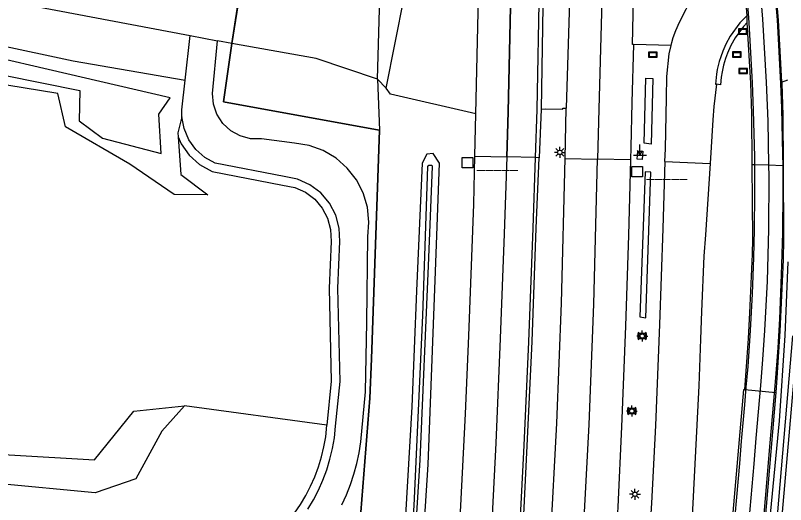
# Model space of a CAD drawing. Extents: x 124000 to 129000, y 395500 to 397503.
# Drawn here: x 124745.4 to 124833.3, y 397160 to 397215.8 of the extents above; entities that cross this region are included whole.
import ezdxf

# ---------------------------------------------------------------- set-up
doc = ezdxf.new("R2010")
doc.units = 0
for name, color, linetype in [('gg-afsc-hekwerk', 7, 'Continuous'), ('gg-afsc-muur', 7, 'Continuous'), ('gg-knt-BGT kruinlijn', 7, 'Continuous'), ('gt-symb-bord', 7, 'Continuous'), ('gt-symb-hm paal', 7, 'Continuous'), ('gt-symb-lichtmast', 7, 'Continuous'), ('gt-symb-markant object', 7, 'Continuous'), ('gx-grn-maaiveld', 7, 'Continuous'), ('gx-knt-lijn weginrichtingselement', 7, 'Continuous')]:
    doc.layers.add(name, color=color, linetype=linetype)

# ---------------------------------------------------------------- blocks, each defined once
blk = doc.blocks.new('gt0-BORD')
at = {"layer": 'gt-symb-bord'}
blk.add_lwpolyline([(-0.5, 0.295), (-0.5, -0.295), (0.5, -0.295), (0.5, 0.295), (-0.5, 0.295)], dxfattribs=at)
blk.add_lwpolyline([(-0.417, -0.212), (0.417, -0.212), (0.417, 0.212), (-0.417, 0.212)], close=True, dxfattribs=at)
blk = doc.blocks.new('gt0-LMAST')
at = {"layer": 'gt-symb-lichtmast'}
for p, q in [((-0.182, 0.173), (-0.447, 0.438)), ((-0.005, 0.246), (-0.005, 0.621)), ((0.172, 0.173), (0.437, 0.438)), ((-0.255, -0.004), (-0.63, -0.004)), ((-0.182, -0.181), (-0.447, -0.446)), ((-0.005, -0.254), (-0.005, -0.629)), ((0.437, -0.446), (0.172, -0.181)), ((0.245, -0.004), (0.62, -0.004))]:
    blk.add_line(p, q, dxfattribs=at)
blk.add_circle((-0.005, -0.004), 0.25, dxfattribs=at)
blk = doc.blocks.new('gt0-HMpaal')
at = {"layer": 'gt-symb-hm paal'}
blk.add_lwpolyline([(-0.6, 0.6), (0.6, 0.6), (0.6, -0.6), (-0.6, -0.6)], close=True, dxfattribs=at)
blk = doc.blocks.new('gt0-MARKOB')
at = {"layer": 'gt-symb-markant object'}
for p, q in [((0, 0), (0, 1.2)), ((-0.75, 0), (0.75, 0)), ((0, 0), (-0.3, 0.52)), ((0, 0), (0.3, 0.52))]:
    blk.add_line(p, q, dxfattribs=at)

msp = doc.modelspace()

# ---------------------------------------------------------------- linework, layer by layer
at = {"layer": 'gg-afsc-hekwerk'}
msp.add_lwpolyline([(124774.888, 397073.073), (124778.544, 397099.23), (124778.986, 397102.392), (124782.98, 397135.974), (124785.856, 397172.14), (124786.014, 397176.607), (124786.937, 397202.711), (124786.926, 397202.713)], dxfattribs=at)
at = {"layer": 'gg-afsc-muur'}
msp.add_lwpolyline([(124786.926, 397202.713), (124769.12, 397205.943), (124770.099, 397212.604), (124771.041, 397218.798), (124772.03, 397225.418)], dxfattribs=at)
at = {"layer": 'gg-knt-BGT kruinlijn'}
for points in [[(124744.044, 397208.989), (124752.708, 397207.237), (124752.633, 397203.786), (124755.318, 397201.798), (124762.031, 397200.056), (124761.73, 397204.56), (124763.041, 397206.421), (124729.225, 397214.239)], [(124734.86, 397166.221), (124754.384, 397165.109), (124758.906, 397170.639), (124764.666, 397171.269)]]:
    msp.add_lwpolyline(points, dxfattribs=at)
at = {"layer": 'gx-grn-maaiveld'}
for p, q in [((124787.696, 397207.503), (124790.039, 397219.245)), ((124797.958, 397204.587), (124798.269, 397219.426)), ((124771.041, 397218.798), (124770.099, 397212.604)), ((124786.713, 397208.551), (124787.002, 397218.335)), ((124741.693, 397218.013), (124765.335, 397213.524)), ((124828.951, 397215.035), (124828.924, 397215.803)), ((124764.759, 397208.43), (124765.335, 397213.524)), ((124765.335, 397213.524), (124768.438, 397212.931)), ((124770.099, 397212.604), (124768.438, 397212.931)), ((124820.245, 397212.407), (124815.953, 397212.51)), ((124786.713, 397208.551), (124786.937, 397202.711)), ((124786.713, 397208.551), (124787.696, 397207.503)), ((124832.867, 397208.207), (124833.564, 397208.483)), ((124805.396, 397205.136), (124805.175, 397199.578)), ((124808.133, 397199.508), (124808.278, 397205.238)), ((124797.844, 397199.75), (124797.958, 397204.587)), ((124797.844, 397199.75), (124801.477, 397199.665)), ((124808.133, 397199.508), (124811.832, 397199.421)), ((124815.623, 397199.331), (124811.832, 397199.421)), ((124819.55, 397199.157), (124824.71, 397198.93)), ((124828.661, 397173.125), (124832.203, 397172.797)), ((124780.94, 397169.071), (124764.666, 397171.269))]:
    msp.add_line(p, q, dxfattribs=at)
for points in [[(124801.477, 397199.665), (124801.648, 397204.803), (124801.931, 397218.564), (124802.042, 397226.77), (124802.168, 397238.749), (124802.175, 397247.682), (124802.181, 397259.638), (124802.019, 397274.636), (124801.88, 397286.592), (124801.727, 397298.073), (124801.711, 397299.476)], [(124812.013, 397299.605), (124812.033, 397298.079), (124812.547, 397250.06), (124812.38, 397224.092), (124812.299, 397216.177), (124811.977, 397205.137), (124811.832, 397199.421)], [(124815.953, 397212.51), (124815.856, 397212.503), (124816.124, 397224.643), (124816.158, 397225.374), (124816.219, 397225.384)], [(124820.245, 397212.407), (124820.34, 397212.73), (124820.49, 397213.306), (124820.77, 397214.095), (124821.189, 397215.056), (124821.975, 397216.528), (124822.274, 397217.133), (124822.492, 397217.714), (124822.657, 397218.288), (124822.74, 397218.739), (124822.782, 397219.139), (124822.781, 397219.593), (124822.704, 397220.21), (124822.536, 397220.812), (124822.294, 397221.382), (124821.511, 397222.691), (124820.097, 397224.65), (124819.325, 397225.883), (124819.207, 397225.866)], [(124828.924, 397215.803), (124828.626, 397219.477), (124828.435, 397221.586), (124828.068, 397225.291)], [(124805.725, 397224.171), (124805.645, 397219.25), (124805.396, 397205.136)], [(124808.68, 397224.123), (124808.6, 397216.25), (124808.278, 397205.238)], [(124832.221, 397218.472), (124832.491, 397215.299), (124832.867, 397208.207)], [(124764.666, 397171.269), (124762.075, 397168.382), (124759.111, 397162.908), (124754.494, 397161.316), (124731.985, 397163.453), (124732.038, 397181.857), (124731.048, 397186.807), (124728.725, 397191.298), (124716.329, 397210.851), (124716.4, 397215.823), (124718.656, 397217.804)], [(124718.656, 397217.804), (124751.959, 397210.644), (124764.759, 397208.43)], [(124828.924, 397215.803), (124828.092, 397214.987), (124827.001, 397213.449), (124826.486, 397212.539), (124826.141, 397211.747), (124825.916, 397211.085), (124825.749, 397210.563), (124825.526, 397209.667), (124825.439, 397209.12), (124825.322, 397207.995), (124825.426, 397207.979)], [(124828.951, 397215.035), (124828.534, 397214.579), (124827.581, 397213.26), (124827.058, 397212.389), (124826.673, 397211.508), (124826.472, 397210.909), (124826.228, 397210.136), (124826.066, 397209.404), (124825.977, 397208.778), (124825.898, 397207.894), (124825.426, 397207.979)], [(124829.517, 397198.821), (124829.483, 397204.589), (124829.364, 397208.092), (124828.951, 397215.035)], [(124782.649, 397159.965), (124783.176, 397161.104), (124783.637, 397162.272), (124784.033, 397163.464), (124784.36, 397164.676), (124784.619, 397165.905), (124784.808, 397167.146), (124785.362, 397172.864), (124785.506, 397180.807), (124785.605, 397190.545), (124785.746, 397192.239), (124785.569, 397193.929), (124785.083, 397195.557), (124784.303, 397197.067), (124783.257, 397198.406), (124781.98, 397199.528), (124780.518, 397200.393), (124778.92, 397200.973), (124777.243, 397201.246), (124773.459, 397201.744), (124772.226, 397201.755), (124771.033, 397202.067), (124769.953, 397202.661), (124769.05, 397203.501), (124768.38, 397204.536), (124767.982, 397205.703), (124767.881, 397206.931), (124768.438, 397212.931)], [(124763.95, 397201.974), (124764.244, 397197.65), (124767.342, 397195.356), (124763.494, 397195.393), (124758.451, 397198.841), (124751.085, 397203.119), (124750.195, 397206.931), (124744.4, 397207.852), (124743.31, 397204.027), (124739.841, 397201.078), (124736.645, 397202.425), (124735.857, 397205.839), (124738.727, 397209.291), (124722.615, 397211.997), (124731.01, 397200.841), (124737.714, 397189.35), (124739.363, 397181.16), (124738.979, 397176.47)], [(124770.099, 397212.604), (124769.12, 397205.943), (124786.926, 397202.713), (124786.937, 397202.711)], [(124786.713, 397208.551), (124779.726, 397210.918), (124770.099, 397212.604)], [(124815.953, 397212.51), (124815.777, 397205.87), (124815.664, 397200.769), (124815.623, 397199.331)], [(124819.55, 397199.157), (124819.593, 397200.602), (124819.735, 397206.433), (124819.777, 397208.854), (124820.015, 397211.422), (124820.245, 397212.407)], [(124764.388, 397204.241), (124764.37, 397204.645), (124764.377, 397205.05), (124764.759, 397208.43)], [(124817.379, 397208.662), (124818.176, 397208.643), (124817.966, 397201.122), (124817.171, 397201.253), (124817.379, 397208.662)], [(124825.426, 397207.979), (124825.146, 397205.415), (124825.029, 397203.891), (124824.71, 397198.93)], [(124832.867, 397208.207), (124832.874, 397208.084), (124833.007, 397204.401), (124833.037, 397198.708)], [(124797.958, 397204.587), (124788.219, 397206.853), (124787.696, 397207.503)], [(124805.396, 397205.136), (124805.94, 397205.144), (124807.885, 397205.138), (124807.889, 397205.235), (124808.278, 397205.238)], [(124764.388, 397204.241), (124763.92, 397202.412), (124763.95, 397201.974)], [(124778.747, 397159.452), (124779.394, 397160.527), (124779.974, 397161.639), (124780.485, 397162.785), (124780.925, 397163.96), (124781.291, 397165.16), (124781.583, 397166.38), (124781.798, 397167.594), (124781.931, 397168.937), (124782.438, 397174.042), (124782.197, 397184.679), (124782.415, 397190.004), (124782.353, 397191.547), (124781.952, 397193.038), (124781.233, 397194.405), (124780.231, 397195.58), (124778.994, 397196.504), (124777.584, 397197.134), (124776.07, 397197.437), (124768.183, 397198.945), (124766.993, 397199.618), (124765.976, 397200.531), (124765.18, 397201.642), (124764.642, 397202.898), (124764.388, 397204.241)], [(124786.937, 397202.711), (124786.014, 397176.607), (124785.856, 397172.14), (124782.98, 397135.974), (124778.986, 397102.392), (124778.544, 397099.23), (124774.888, 397073.073)], [(124763.95, 397201.974), (124764.304, 397201.148), (124765.227, 397199.86), (124766.406, 397198.801), (124767.834, 397197.994), (124775.878, 397196.456), (124777.278, 397196.175), (124778.485, 397195.636), (124779.543, 397194.846), (124780.4, 397193.841), (124781.015, 397192.671), (124781.358, 397191.395), (124781.414, 397190.004), (124781.197, 397184.688), (124781.437, 397174.08), (124780.94, 397169.071)], [(124792.493, 397164.558), (124793.336, 397186.577), (124793.792, 397198.942), (124793.076, 397200.057), (124792.365, 397199.989), (124791.803, 397198.95), (124791.169, 397184.399), (124790.651, 397171.158), (124788.93, 397141.752), (124788.332, 397129.544), (124788.772, 397128.809), (124789.791, 397128.882), (124790.18, 397129.594), (124791.418, 397147.308), (124792.493, 397164.558)], [(124792.053, 397100.524), (124792.546, 397105.919), (124793.395, 397116.661), (124794.283, 397128.623), (124794.888, 397137.357), (124795.489, 397146.444), (124796.008, 397155.393), (124796.758, 397170.354), (124797.147, 397179.258), (124797.715, 397194.281), (124797.844, 397199.75)], [(124801.477, 397199.665), (124801.186, 397190.886), (124800.743, 397178.945), (124800.219, 397166.983), (124799.608, 397155.046), (124799.03, 397145.628), (124798.481, 397136.86), (124797.88, 397128.167), (124796.99, 397116.232), (124796.117, 397105.554), (124795.627, 397100.198)], [(124805.175, 397199.578), (124804.728, 397199.588), (124801.477, 397199.665)], [(124817.003, 397200.33), (124816.96, 397199.396), (124816.383, 397199.425), (124816.438, 397200.347), (124817.003, 397200.33)], [(124799.258, 397099.866), (124799.742, 397105.283), (124800.619, 397115.925), (124801.525, 397128.032), (124802.127, 397136.933), (124802.696, 397145.813), (124803.25, 397154.939), (124803.826, 397166.677), (124804.372, 397178.604), (124804.856, 397191.558), (124805.175, 397199.578)], [(124802.693, 397099.552), (124803.862, 397114.352), (124805.745, 397142.189), (124807.181, 397169.292), (124807.714, 397182.987), (124808.133, 397199.508)], [(124806.378, 397099.216), (124807.552, 397114.081), (124809.438, 397141.966), (124810.877, 397169.122), (124811.412, 397182.868), (124811.832, 397199.421)], [(124815.623, 397199.331), (124815.376, 397190.733), (124815.034, 397180.336), (124814.576, 397168.863), (124814.158, 397159.742), (124813.763, 397152.182), (124813.263, 397143.33), (124812.64, 397133.59), (124812.135, 397125.781), (124811.451, 397116.218), (124811.177, 397112.27), (124811.095, 397110.289), (124811.191, 397109.366), (124811.339, 397108.98), (124811.631, 397108.819), (124812.527, 397108.655), (124812.673, 397108.826)], [(124819.55, 397199.157), (124819.322, 397191.497), (124818.937, 397180.542), (124818.477, 397169.025), (124818.007, 397160.137), (124817.508, 397152.544), (124816.784, 397143.505), (124815.742, 397132.649), (124814.96, 397125.558), (124813.712, 397115.965), (124813.219, 397112.169), (124812.673, 397108.826)], [(124824.71, 397198.93), (124824.187, 397190.79), (124823.99, 397188.358), (124823.72, 397182.019), (124823.602, 397178.867), (124823.421, 397173.546), (124822.568, 397157.186), (124821.361, 397141.341), (124820.11, 397129.03), (124818.402, 397115.016), (124816.619, 397102.542), (124815.973, 397098.339)], [(124828.661, 397173.125), (124828.869, 397175.754), (124829.092, 397178.958), (124829.256, 397181.861), (124829.524, 397188.562), (124829.568, 397190.3), (124829.517, 397198.821)], [(124829.517, 397198.821), (124829.763, 397198.813), (124831.372, 397198.761), (124832.988, 397198.709), (124833.037, 397198.708)], [(124789.1, 397130.056), (124789.023, 397130.472), (124789.492, 397138.147), (124790.89, 397159.871), (124791.91, 397181.556), (124792.468, 397198.573), (124792.58, 397198.74), (124792.94, 397198.725), (124792.971, 397198.565), (124792.516, 397187.236), (124791.565, 397165.104), (124790.277, 397144.363), (124789.555, 397130.34), (124789.384, 397130.014), (124789.1, 397130.056)], [(124817.298, 397197.988), (124816.685, 397181.418), (124817.348, 397181.303), (124817.943, 397197.923), (124817.298, 397197.988)], [(124833.037, 397198.708), (124833.081, 397190.289), (124833.038, 397187.93), (124832.669, 397179.781), (124832.308, 397174.447), (124832.203, 397172.797)], [(124833.592, 397151.797), (124832.183, 397137.766), (124829.788, 397119.595), (124826.61, 397097.963), (124824.265, 397083.356), (124823.459, 397082.467), (124822.605, 397082.75), (124822.412, 397083.719), (124824.719, 397099.103), (124826.864, 397114.299), (124828.375, 397125.994), (124830.027, 397141.258), (124831.424, 397156.915), (124832.636, 397169.565), (124833.27, 397179.301), (124833.609, 397187.707)], [(124834.102, 397179.257), (124833.288, 397169.452), (124832.217, 397156.933), (124830.916, 397141.146), (124829.393, 397128.559), (124827.243, 397111.868), (124824.942, 397095.048), (124823.525, 397086.424), (124823.233, 397084.201), (124823.531, 397084.16), (124823.858, 397086.09), (124825.298, 397095.537), (124828.888, 397119.593), (124831.026, 397138.621), (124832.319, 397151.689), (124834.465, 397176.119)], [(124820.123, 397097.96), (124820.735, 397101.935), (124822.587, 397114.679), (124824.332, 397128.574), (124825.822, 397142.192), (124827.162, 397156.872), (124828.552, 397173.108), (124828.661, 397173.125)], [(124832.203, 397172.797), (124830.9, 397157.533), (124829.438, 397141.65), (124827.763, 397126.481), (124826.261, 397114.488), (124824.827, 397104.624), (124823.741, 397097.63)], [(124777.229, 397159.012), (124777.906, 397159.994), (124778.522, 397161.017), (124779.073, 397162.074), (124779.559, 397163.164), (124779.978, 397164.282), (124780.326, 397165.423), (124780.604, 397166.584), (124780.807, 397167.731), (124780.94, 397169.071)]]:
    msp.add_lwpolyline(points, dxfattribs=at)
at = {"layer": 'gx-knt-lijn weginrichtingselement'}
for points in [[(124801.727, 397298.073), (124801.88, 397286.592), (124802.019, 397274.636), (124802.181, 397259.638), (124802.175, 397247.682), (124802.168, 397238.749), (124802.042, 397226.77), (124801.931, 397218.564), (124801.648, 397204.803), (124801.477, 397199.665), (124801.186, 397190.886), (124800.743, 397178.945), (124800.219, 397166.983), (124799.608, 397155.046), (124799.03, 397145.628), (124798.481, 397136.86), (124797.88, 397128.167), (124796.99, 397116.232), (124796.117, 397105.554), (124795.627, 397100.198), (124794.838, 397091.583), (124793.772, 397080.49), (124792.634, 397069.481)], [(124805.19, 397219.294), (124804.912, 397205.094), (124804.728, 397199.588), (124804.459, 397191.552), (124803.98, 397178.573), (124803.44, 397166.73), (124802.819, 397154.917), (124802.282, 397145.871), (124801.719, 397136.946), (124801.105, 397127.897), (124800.186, 397115.87), (124799.346, 397105.252), (124798.867, 397099.902), (124798.088, 397091.191), (124796.986, 397079.888), (124795.848, 397069.031), (124794.092, 397053.296), (124793.359, 397047.038), (124791.835, 397034.538), (124790.748, 397026.333), (124787.672, 397003.903)], [(124828.818, 397219.148), (124829.133, 397215.001), (124829.501, 397208.122), (124829.631, 397204.957), (124829.759, 397199.673), (124829.763, 397198.813), (124829.776, 397195.517), (124829.735, 397191.336), (124829.66, 397188.209), (124829.494, 397184.048), (124829.285, 397179.854), (124829.028, 397175.755), (124828.788, 397173.376), (124828.623, 397171.367), (124828.252, 397167.235), (124828.05, 397164.686), (124827.184, 397154.841)], [(124830.425, 397218.659), (124830.694, 397215.414), (124831.099, 397208.194), (124831.282, 397203.751), (124831.372, 397198.761), (124831.395, 397197.451), (124831.374, 397191.428), (124831.203, 397185.494), (124830.909, 397179.855), (124830.676, 397176.544), (124830.463, 397173.582), (124829.925, 397167.579), (124829.704, 397164.62), (124828.914, 397155.587), (124828.142, 397146.905), (124826.871, 397134.932), (124825.461, 397122.926), (124824.674, 397116.782), (124823.462, 397107.86), (124821.939, 397097.795), (124821.673, 397096.038), (124818.411, 397075.376), (124817.395, 397069.022)], [(124832.108, 397218.43), (124832.357, 397215.327), (124832.753, 397208.071), (124832.87, 397205.237), (124832.984, 397199.936), (124832.988, 397198.709), (124832.998, 397195.749), (124832.954, 397191.039), (124832.871, 397187.373), (124832.751, 397184.162), (124832.624, 397181.177), (124832.427, 397177.892), (124832.183, 397174.473), (124831.81, 397170.479), (124831.498, 397166.622), (124831.257, 397163.855), (124830.48, 397154.814)]]:
    msp.add_lwpolyline(points, dxfattribs=at)

# ---------------------------------------------------------------- block references
at = {"layer": 'gt-symb-bord'}
for p in [(124828.446, 397213.992), (124818.151, 397211.344), (124827.749, 397211.358), (124828.483, 397209.475), (124816.951, 397179.222), (124815.768, 397170.671)]:
    msp.add_blockref('gt0-BORD', p, dxfattribs=at)
at = {"layer": 'gt-symb-hm paal'}
for p in [(124797.003, 397199.017), (124816.367, 397197.985)]:
    msp.add_blockref('gt0-HMpaal', p, dxfattribs=at)
at = {"layer": 'gt-symb-lichtmast'}
for p in [(124807.547, 397200.191), (124816.951, 397179.222), (124815.768, 397170.671), (124816.127, 397161.165)]:
    msp.add_blockref('gt0-LMAST', p, dxfattribs=at)
at = {"layer": 'gt-symb-markant object'}
msp.add_blockref('gt0-MARKOB', (124816.695, 397199.88), dxfattribs=at)

# ---------------------------------------------------------------- texts
at = {"layer": 'gt-symb-hm paal'}
for p in [(124798.084, 397198.413), (124817.448, 397197.381)]:
    msp.add_text('_____', height=1.25, dxfattribs=at).set_placement(p)

doc.saveas('drawing.dxf')
